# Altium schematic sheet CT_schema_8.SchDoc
size 274 x 160 mm
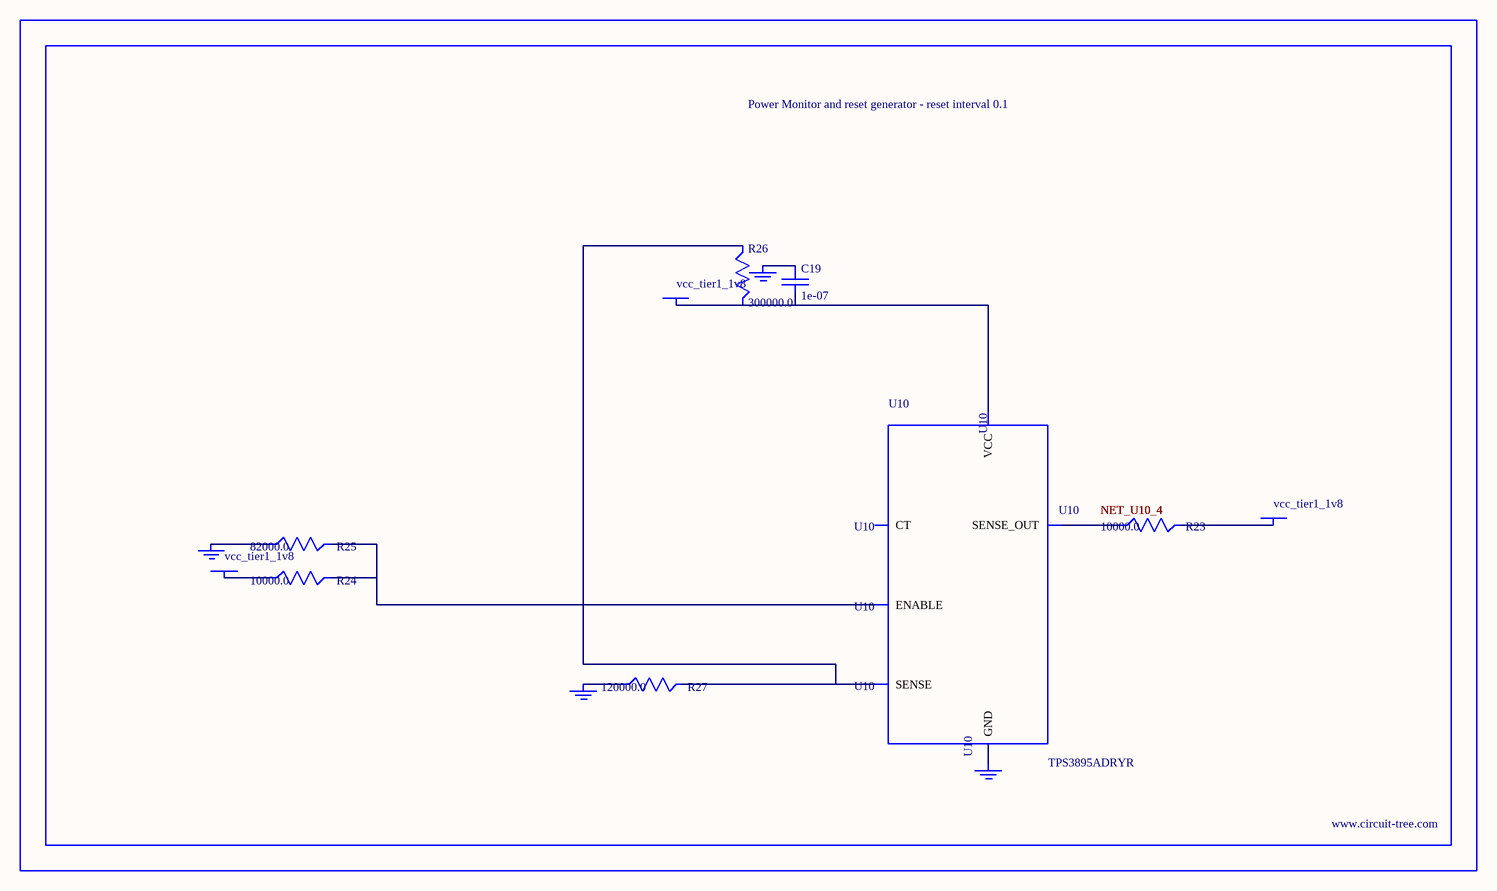
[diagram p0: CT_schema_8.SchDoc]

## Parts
BORDER7  (no value)
C19  1e-07  [C0402]
GND_INSTANCE_7_0  (no value)
GND_INSTANCE_7_1  (no value)
GND_INSTANCE_7_2  (no value)
GND_INSTANCE_7_3  (no value)
POWER_INSTANCE_7_0  vcc_tier1_1v8
POWER_INSTANCE_7_1  vcc_tier1_1v8
POWER_INSTANCE_7_2  vcc_tier1_1v8
R23  10000.0  [R0603]
R24  10000.0  [R0603]
R25  82000.0  [R0603]
R26  300000.0  [R0603]
R27  120000.0  [R0603]
U10  TPS3895ADRYR  [SON-6]

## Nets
NetC19_1: C19.1 GND_INSTANCE_7_2.0(GND)
NetC19_2: C19.2 POWER_INSTANCE_7_2.0(PWR) R26.2 U10.6(VCC)
NetGND_INSTANCE_7_0_0: GND_INSTANCE_7_0.0(GND) R25.1
NetGND_INSTANCE_7_1_0: GND_INSTANCE_7_1.0(GND) R27.1
NetGND_INSTANCE_7_3_0: GND_INSTANCE_7_3.0(GND) U10.2(GND)
NetPOWER_INSTANCE_7_0_0: POWER_INSTANCE_7_0.0(PWR) R24.1
NetPOWER_INSTANCE_7_1_0: POWER_INSTANCE_7_1.0(PWR) R23.2
NetR23_1: R23.1 U10.4(SENSE_OUT)
NetR24_2: R24.2 R25.2 U10.1(ENABLE)
NetR26_1: R26.1 R27.2 U10.3(SENSE)

Not connected (* = marked no-connect by the designer): U10 5(CT)

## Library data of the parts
BORDER7 = BORDER_PAGE7
C19 = C0402C104K3RACTU
GND_INSTANCE_7_0-GND_INSTANCE_7_3 = GND
POWER_INSTANCE_7_0-POWER_INSTANCE_7_2 = PWR
R23 R24 = RC0603JR-0710KL
R25 = RC0603JR-0782KL
R26 = RC0603JR-07300KL
R27 = RC0603JR-07120KL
